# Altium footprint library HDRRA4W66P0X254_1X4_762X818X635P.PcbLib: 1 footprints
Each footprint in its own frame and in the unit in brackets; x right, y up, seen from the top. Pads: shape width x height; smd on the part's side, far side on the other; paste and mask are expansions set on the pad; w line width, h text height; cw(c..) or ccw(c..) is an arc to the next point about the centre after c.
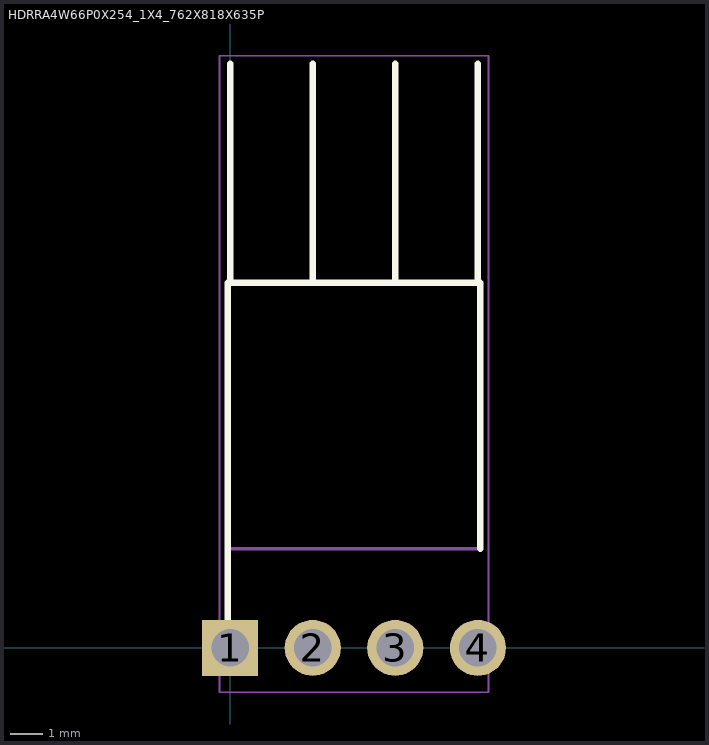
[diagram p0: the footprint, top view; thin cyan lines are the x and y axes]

## HDRRA4W66P0X254_1X4_762X818X635P [mm]
pads (4):
  rect 1.725x1.725 / inner round 1.725 / far side rect 1.725x1.725 hole 1.15: 1(0,0)
  round 1.725 hole 1.15: 2(2.54,0) 3(5.08,0) 4(7.62,0)
Top Overlay:
  lines w0.2: -0.075,0 -0.075,11.23 7.695,11.23 7.695,3.05 ; 0,11.23 0,17.96 ; 2.54,11.23 2.54,17.96 ; 5.08,11.23 5.08,17.96 ; 7.62,11.23 7.62,17.96
Mechanical 15:
  lines w0.1: -0.075,3.05 -0.075,11.23 7.695,11.23 7.695,3.05 -0.075,3.05
Mechanical 20:
  lines w0.05: -0.325,-1.362 7.945,-1.362 7.945,18.21 -0.325,18.21 -0.325,-1.362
